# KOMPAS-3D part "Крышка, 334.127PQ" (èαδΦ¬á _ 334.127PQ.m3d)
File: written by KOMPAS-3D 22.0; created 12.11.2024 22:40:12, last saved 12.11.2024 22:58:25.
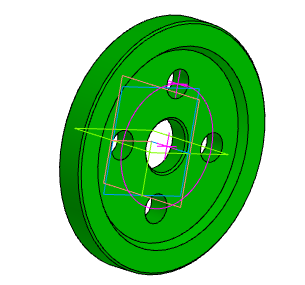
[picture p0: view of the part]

Document properties: Автор: aleksander.larionov.10@gmail.com; Полное имя файла: C:\Мои папки\Работа\Крышки, фланцы\334.127PQ\Крышка _ 334.127PQ.m3d

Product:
- Part/product: Крышка  | designation 334.127PQ
    Материал: Сталь 45 ГОСТ 1050-2013 (density 7810 kg/m3)
    Масса: 0.895808

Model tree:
1. Эскиз:1
2. Элемент вращения:1
     Угол 1 = 360
3. Эскиз:2  (with: Элемент вращения:1)
4. Отверстие:1  (with: Элемент вращения:1)
     Глубина выреза = 10; Диаметр отверстия = 14; Угол конуса дна = 118; Расстояние 2 = 29
5. Массив по концентрической сетке:1  (with: Отверстие:1, Эскиз:2)  (4 pattern instances)
     Шаг 2 = 360
6. Фаска:1  (with: Элемент вращения:1)
     Угол = 45; Длина 1 = 1; Длина 2 = 1
7. Отверстие:2  (with: Элемент вращения:1)
     Глубина выреза = 10; Диаметр отверстия = 25; Угол конуса дна = 118
8. Фаска:2  (with: Отверстие:2)  (labels: Сталь 45 ГОСТ 1050-2013)
     Угол = 45; Длина 1 = 1; Длина 2 = 1

Expressions: 118/2; 95/2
